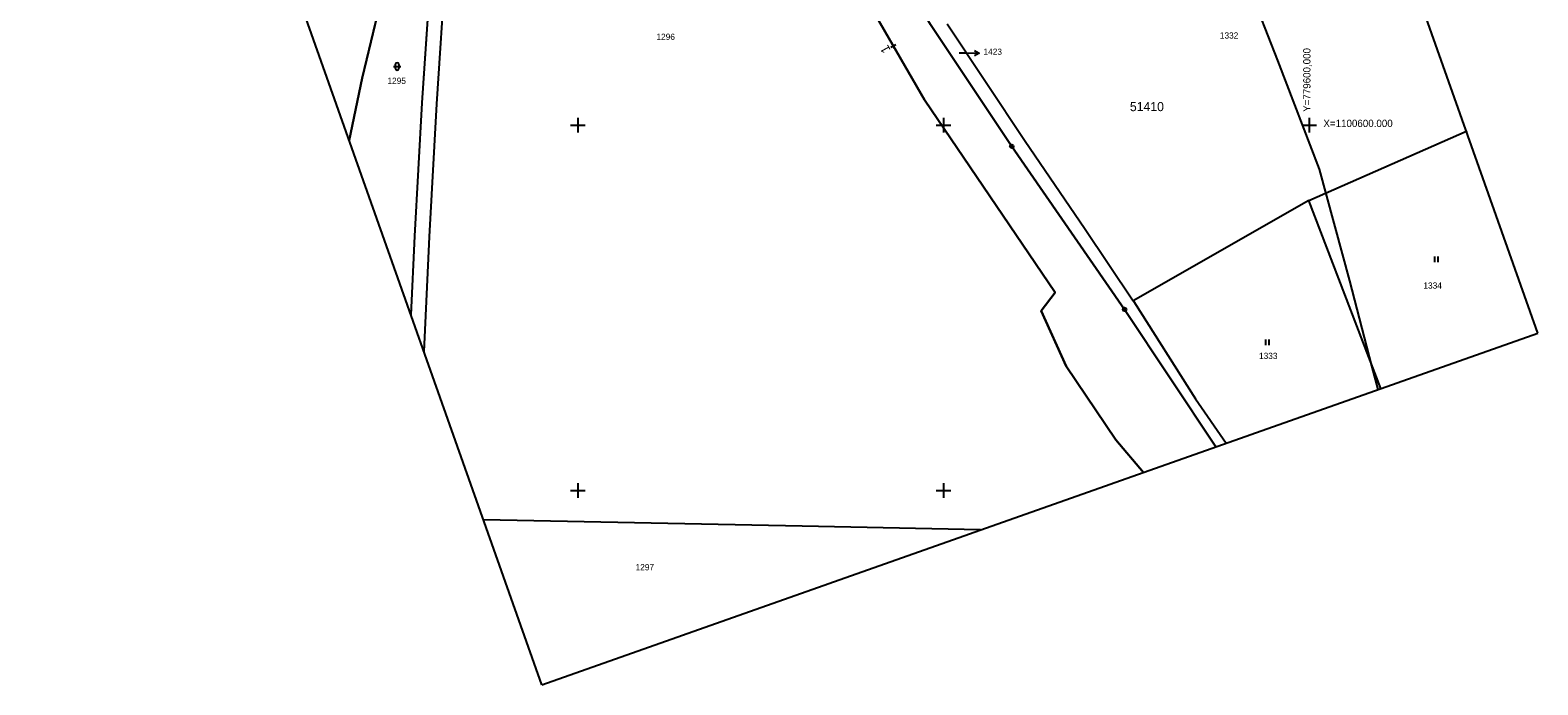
# Model space of a CAD drawing. Extents: x -779950 to -779537, y -1100753 to -1100261.
# Drawn here: x -779949.8 to -779537.4, y -1100753.2 to -1100574 of the extents above; entities that cross this region are included whole.
import ezdxf

# ---------------------------------------------------------------- set-up
doc = ezdxf.new("R2010")
doc.units = 0
for name, color, linetype in [('BPEJ', 7, 'Continuous'), ('Groma (60)', 7, 'Continuous'), ('Katastr_HRANICE DRÁHY', 7, 'Continuous'), ('Katastr_Hranice parcel', 7, 'Continuous'), ('Katastr_Parcelní čísla', 7, 'Continuous'), ('Katastr_Značky kultur', 7, 'Continuous'), ('čtvercová síť', 7, 'Continuous')]:
    doc.layers.add(name, color=color, linetype=linetype)

# ---------------------------------------------------------------- blocks, each defined once
blk = doc.blocks.new('POINT_DISPLAY')
for p, q in [((-0.56, -0.56), (0.56, 0.56)), ((-0.56, 0.56), (0.56, -0.56))]:
    blk.add_line(p, q)
blk = doc.blocks.new('C691')
at = {"layer": 'čtvercová síť'}
for p, q in [((-0.5, 0), (0.5, 0)), ((0, 0.5), (0, -0.5))]:
    blk.add_line(p, q, dxfattribs=at)

msp = doc.modelspace()

# ---------------------------------------------------------------- linework, layer by layer
at = {"layer": 'BPEJ'}
for points in [[(-779625.47, -1100688.02), (-779650.47, -1100650.42), (-779681.32, -1100605.77), (-779703.57, -1100572.42), (-779721.36, -1100542.95), (-779739.67, -1100497.93), (-779743.7, -1100484.06), (-779744.94, -1100484.43), (-779746.21, -1100480.3), (-779744.9, -1100479.92), (-779754.11, -1100448.23), (-779757.39, -1100424.96), (-779758.99, -1100393.31), (-779756.39, -1100373.64), (-779756.29, -1100371.78), (-779755.9, -1100364.14)], [(-779890.82, -1100524.22), (-779886.08, -1100516.97), (-779866.53, -1100485.67), (-779853.07, -1100465.22), (-779850.53, -1100466.64), (-779843.03, -1100470.81), (-779844.01, -1100494.22), (-779844.61, -1100508.67), (-779845.33, -1100516.55), (-779846.53, -1100529.73), (-779848.96, -1100543.96), (-779849.67, -1100548.08), (-779851.45, -1100555.5), (-779859.03, -1100587.13), (-779862.58, -1100604.13)], [(-779645.29, -1100695.03), (-779652.86, -1100686.16), (-779666.46, -1100665.96), (-779673.24, -1100650.81), (-779669.47, -1100645.82), (-779705.21, -1100593.05), (-779732.47, -1100545.72)], [(-779840.13, -1100556.13), (-779842.69, -1100593.88), (-779844.69, -1100630.38), (-779845.7, -1100651.91)], [(-779616.56, -1100561.88), (-779608.63, -1100582.25), (-779597.25, -1100612), (-779588.94, -1100642.63), (-779582.94, -1100665.88), (-779581.18, -1100672.37)]]:
    msp.add_lwpolyline(points, dxfattribs=at)
at = {"layer": 'Defpoints'}
for p, q in [((-779537.42, -1100656.91), (-779677.36, -1100260.91)), ((-779809.9, -1100753.2), (-779949.84, -1100357.2)), ((-779809.9, -1100753.2), (-779537.42, -1100656.91))]:
    msp.add_line(p, q, dxfattribs=at)
at = {"layer": 'Katastr_HRANICE DRÁHY'}
for points in [[(-779732.47, -1100545.72), (-779705.21, -1100593.05)], [(-779703.57, -1100572.42), (-779681.32, -1100605.77)], [(-779705.21, -1100593.05), (-779669.47, -1100645.82)], [(-779681.32, -1100605.77), (-779650.47, -1100650.42)], [(-779669.47, -1100645.82), (-779673.24, -1100650.81)], [(-779673.24, -1100650.81), (-779666.46, -1100665.96)], [(-779650.47, -1100650.42), (-779625.47, -1100688.02)], [(-779666.46, -1100665.96), (-779652.86, -1100686.16)], [(-779652.86, -1100686.16), (-779645.29, -1100695.03)]]:
    msp.add_lwpolyline(points, dxfattribs=at)
at = {"layer": 'Katastr_Hranice parcel'}
for points in [[(-779859.03, -1100587.13), (-779849.67, -1100548.08)], [(-779840.15, -1100556.07), (-779842.69, -1100593.89)], [(-779836.18, -1100556.59), (-779838.7, -1100594.13)], [(-779698.96, -1100572.26), (-779677.7, -1100604.31)], [(-779862.58, -1100604.13), (-779859.03, -1100587.13)], [(-779842.69, -1100593.89), (-779844.7, -1100630.36)], [(-779838.7, -1100594.13), (-779840.69, -1100630.56)], [(-779677.7, -1100604.31), (-779661.45, -1100628.16)], [(-779600.02, -1100620.55), (-779556.76, -1100601.51)], [(-779600.02, -1100620.55), (-779648.09, -1100648.04)], [(-779580.36, -1100672.08), (-779600.02, -1100620.55)], [(-779661.45, -1100628.16), (-779648.09, -1100648.04)], [(-779844.7, -1100630.36), (-779845.7, -1100651.89)], [(-779840.69, -1100630.56), (-779842.16, -1100661.92)], [(-779648.09, -1100648.04), (-779647.97, -1100648.22)], [(-779647.97, -1100648.22), (-779631.04, -1100674.92)], [(-779631.04, -1100674.92), (-779622.7, -1100687.05)], [(-779738.63, -1100709.79), (-779825.87, -1100708.02)], [(-779689.85, -1100710.77), (-779738.63, -1100709.79)]]:
    msp.add_lwpolyline(points, dxfattribs=at)
at = {"layer": 'Katastr_Parcelní čísla'}
for p, q in [((-779691.49, -1100579.49), (-779690.2, -1100580.26)), ((-779695.68, -1100580.17), (-779694.2, -1100580.19))]:
    msp.add_line(p, q, dxfattribs=at)
msp.add_lwpolyline([(-779694.2, -1100580.19), (-779690.2, -1100580.26), (-779691.51, -1100580.99)], dxfattribs=at)
at = {"layer": 'Katastr_Značky kultur'}
for p, q in [((-779850.47, -1100583.89), (-779848.47, -1100583.89)), ((-779849.97, -1100583.39), (-779849.97, -1100584.39)), ((-779848.97, -1100583.39), (-779848.97, -1100584.39)), ((-779681.37, -1100605.77), (-779681.27, -1100605.77)), ((-779565.72, -1100635.94), (-779565.72, -1100637.44)), ((-779564.72, -1100637.44), (-779564.72, -1100635.94)), ((-779650.52, -1100650.42), (-779650.42, -1100650.42)), ((-779611.92, -1100658.68), (-779611.92, -1100660.18)), ((-779610.92, -1100660.18), (-779610.92, -1100658.68))]:
    msp.add_line(p, q, dxfattribs=at)
for centre in [(-779681.32, -1100605.77), (-779650.47, -1100650.42)]:
    msp.add_circle(centre, 0.499, dxfattribs=at)
for centre, start, end in [((-779849.47, -1100583.39), 0, 180), ((-779849.47, -1100584.39), 180, 0)]:
    msp.add_arc(centre, 0.5, start, end, dxfattribs=at)

# ---------------------------------------------------------------- block references
at = {"layer": 'Groma (60)', "rotation": 70.53751088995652}
msp.add_blockref('POINT_DISPLAY', (-779713.72, -1100578.27), dxfattribs=at)
at = {"layer": 'čtvercová síť', "xscale": 4, "yscale": 4}
for p in [(-779800, -1100600), (-779700, -1100600), (-779600, -1100600), (-779800, -1100700), (-779700, -1100700)]:
    msp.add_blockref('C691', p, dxfattribs=at)

# ---------------------------------------------------------------- texts
at = {"layer": 'BPEJ'}
msp.add_text('51410', height=2.5, dxfattribs=at).set_placement((-779649, -1100596.13))
at = {"layer": 'Groma (60)'}
msp.add_text('1', height=2.5, rotation=118.7599, dxfattribs=at).set_placement((-779714.38, -1100579.4))
at = {"layer": 'Katastr_Parcelní čísla'}
for s, p in [('1296', (-779778.52, -1100576.62)), ('1332', (-779624.4, -1100576.26)), ('1423', (-779689.06, -1100580.71)), ('1295', (-779852.11, -1100588.67)), ('1334', (-779568.72, -1100644.73)), ('1333', (-779613.69, -1100663.98)), ('1297', (-779784.23, -1100721.83))]:
    msp.add_text(s, height=1.7, dxfattribs=at).set_placement(p)
at = {"layer": 'čtvercová síť'}
msp.add_text('Y=779600,000', height=2, rotation=90, dxfattribs=at).set_placement((-779599.61, -1100596.33))
msp.add_text('X=1100600.000', height=2, dxfattribs=at).set_placement((-779596.08, -1100600.48))

doc.saveas('drawing.dxf')
